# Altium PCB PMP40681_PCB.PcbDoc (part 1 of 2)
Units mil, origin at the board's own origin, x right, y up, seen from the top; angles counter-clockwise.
Board outline 1574.8 x 1574.8 mil, 4 copper layers (Top Layer, Signal Layer 1, Signal Layer 2, Bottom Layer), stack 67.2 mil thick; 42 components, 23 nets, 157 pads, 377 vias.
Unrouted connection lines stored in the file: 17.
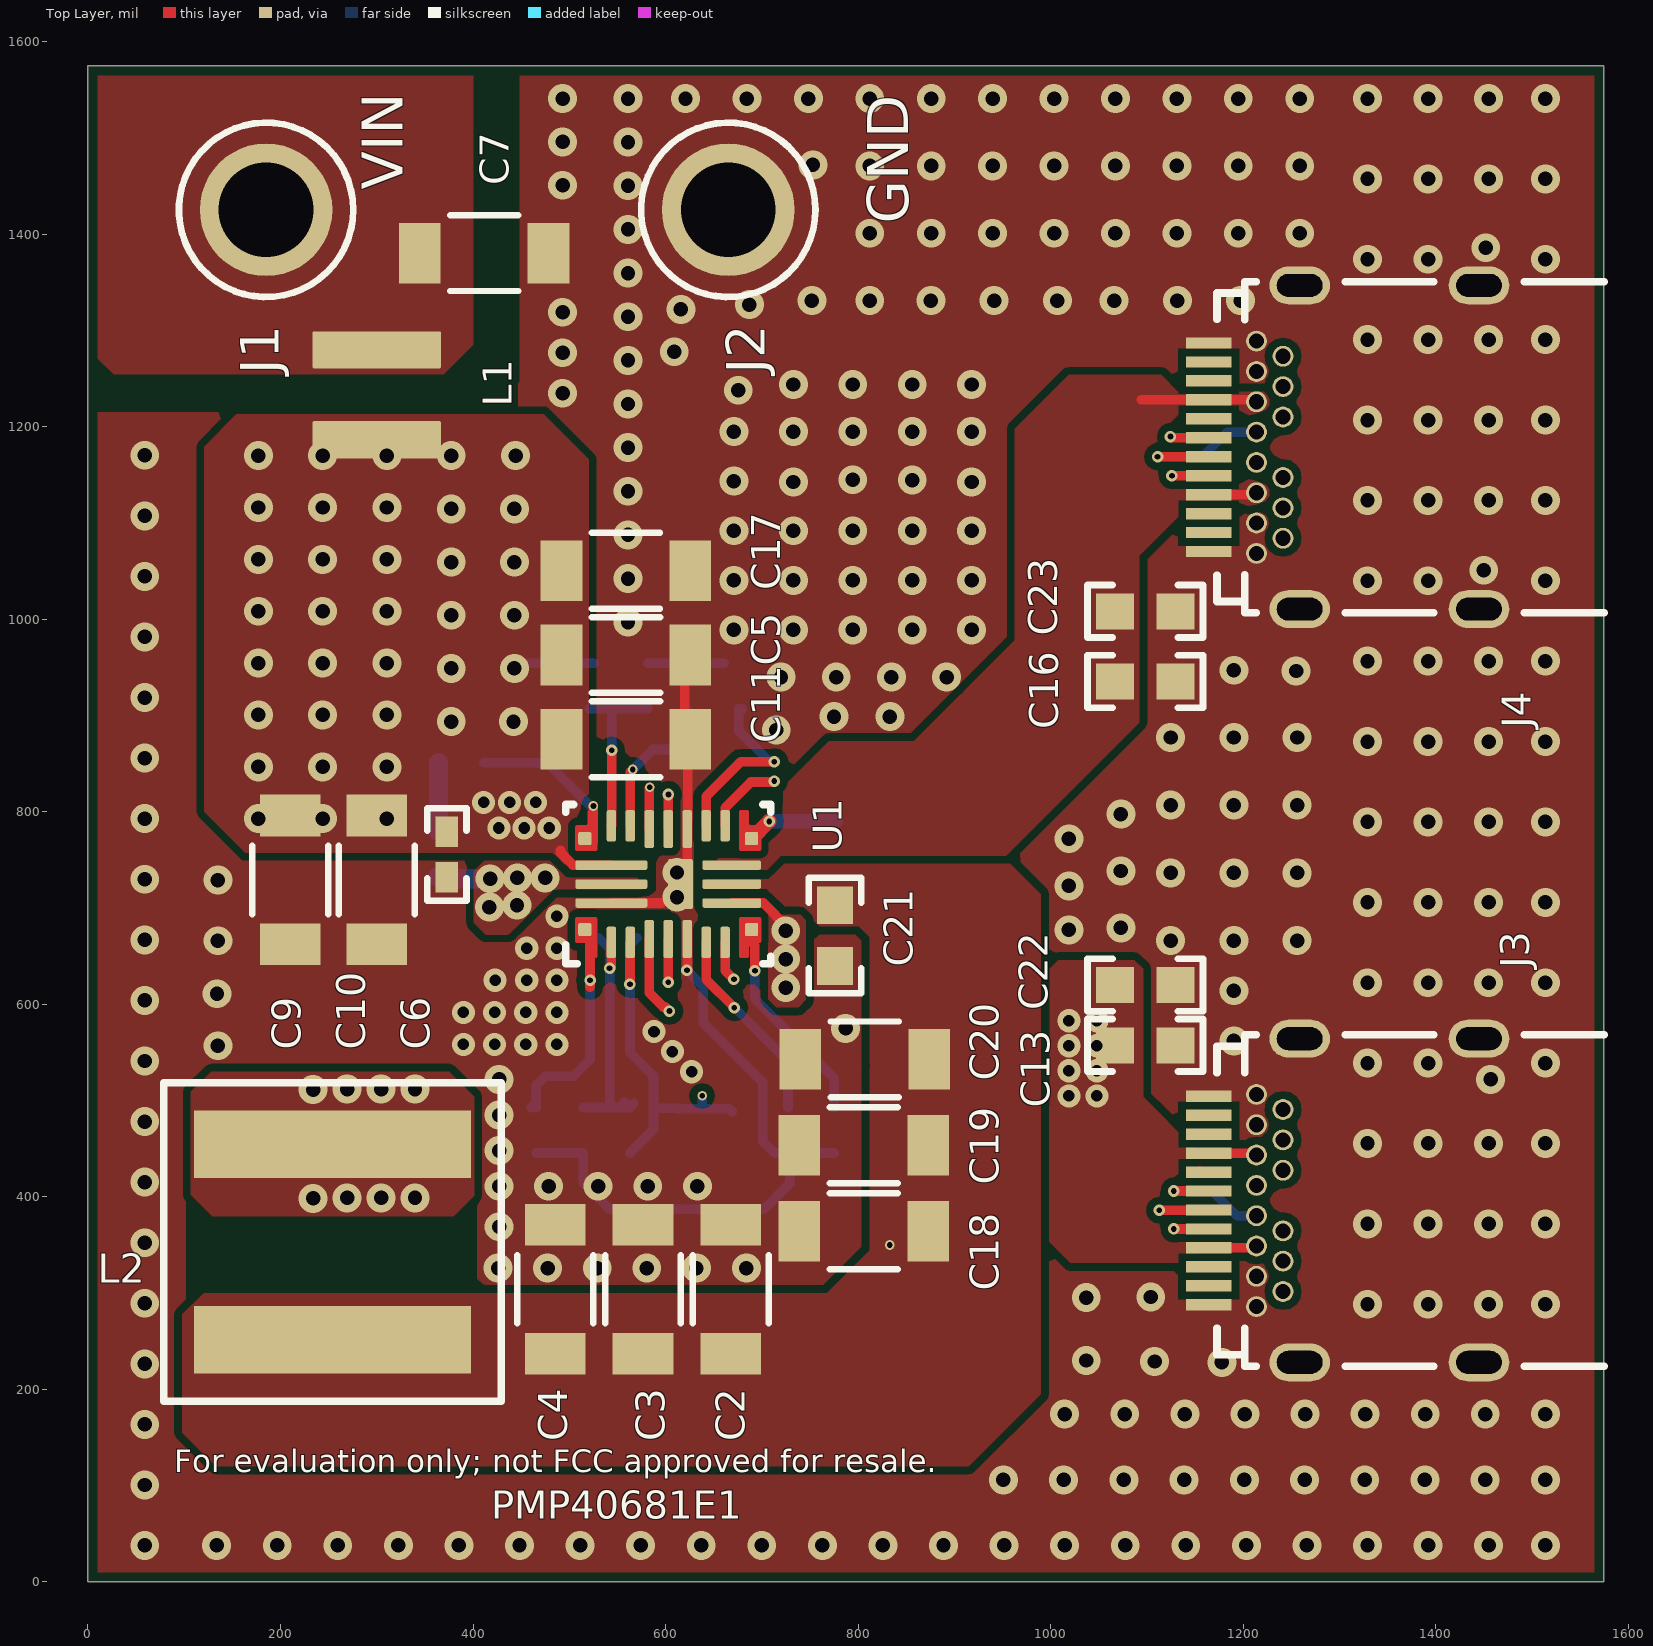
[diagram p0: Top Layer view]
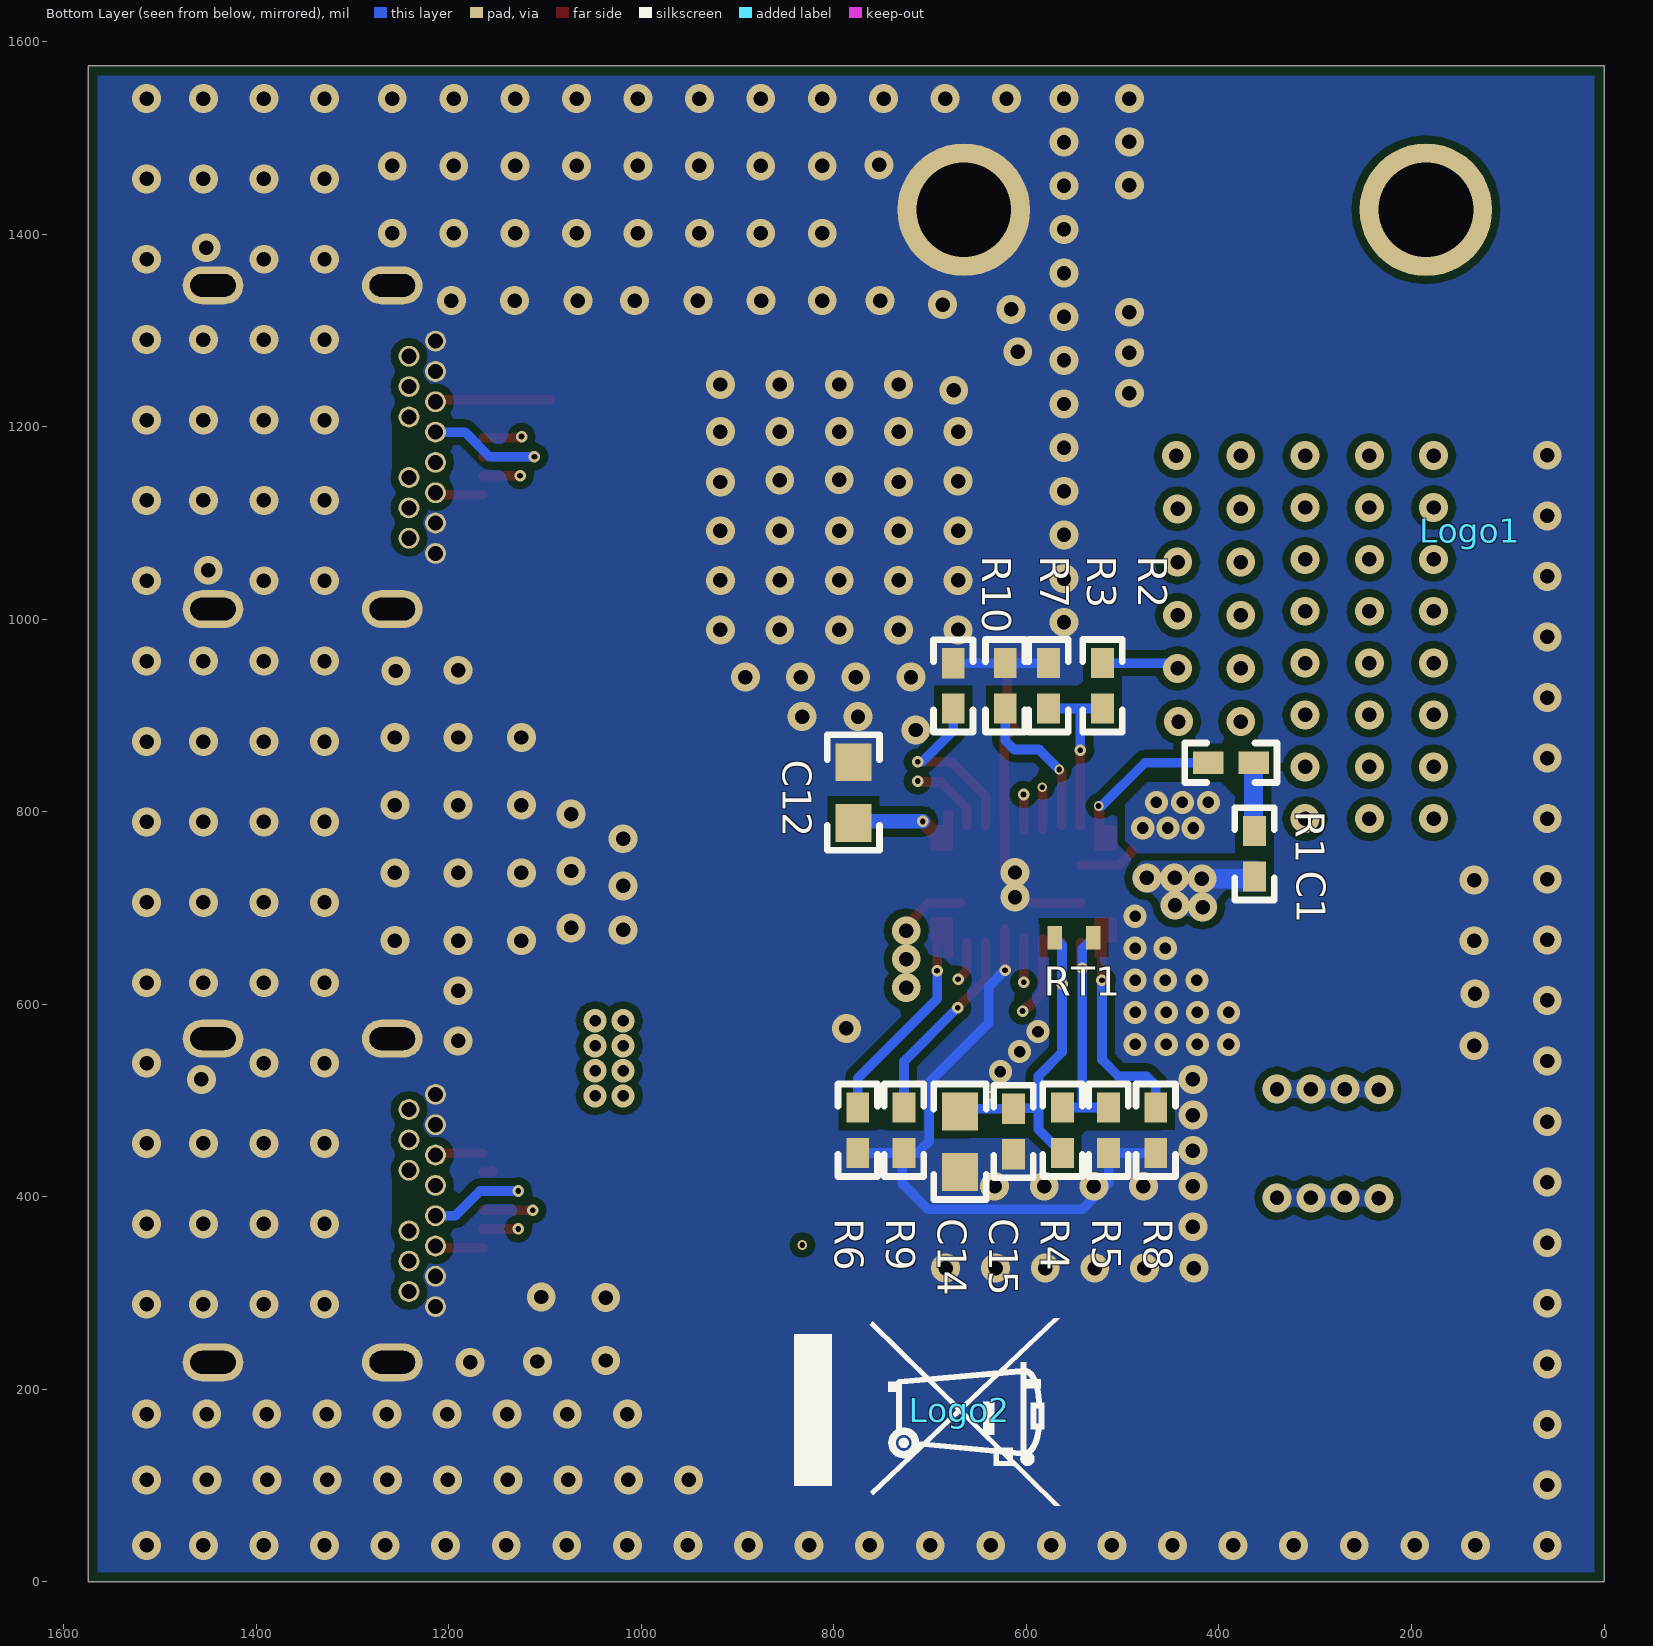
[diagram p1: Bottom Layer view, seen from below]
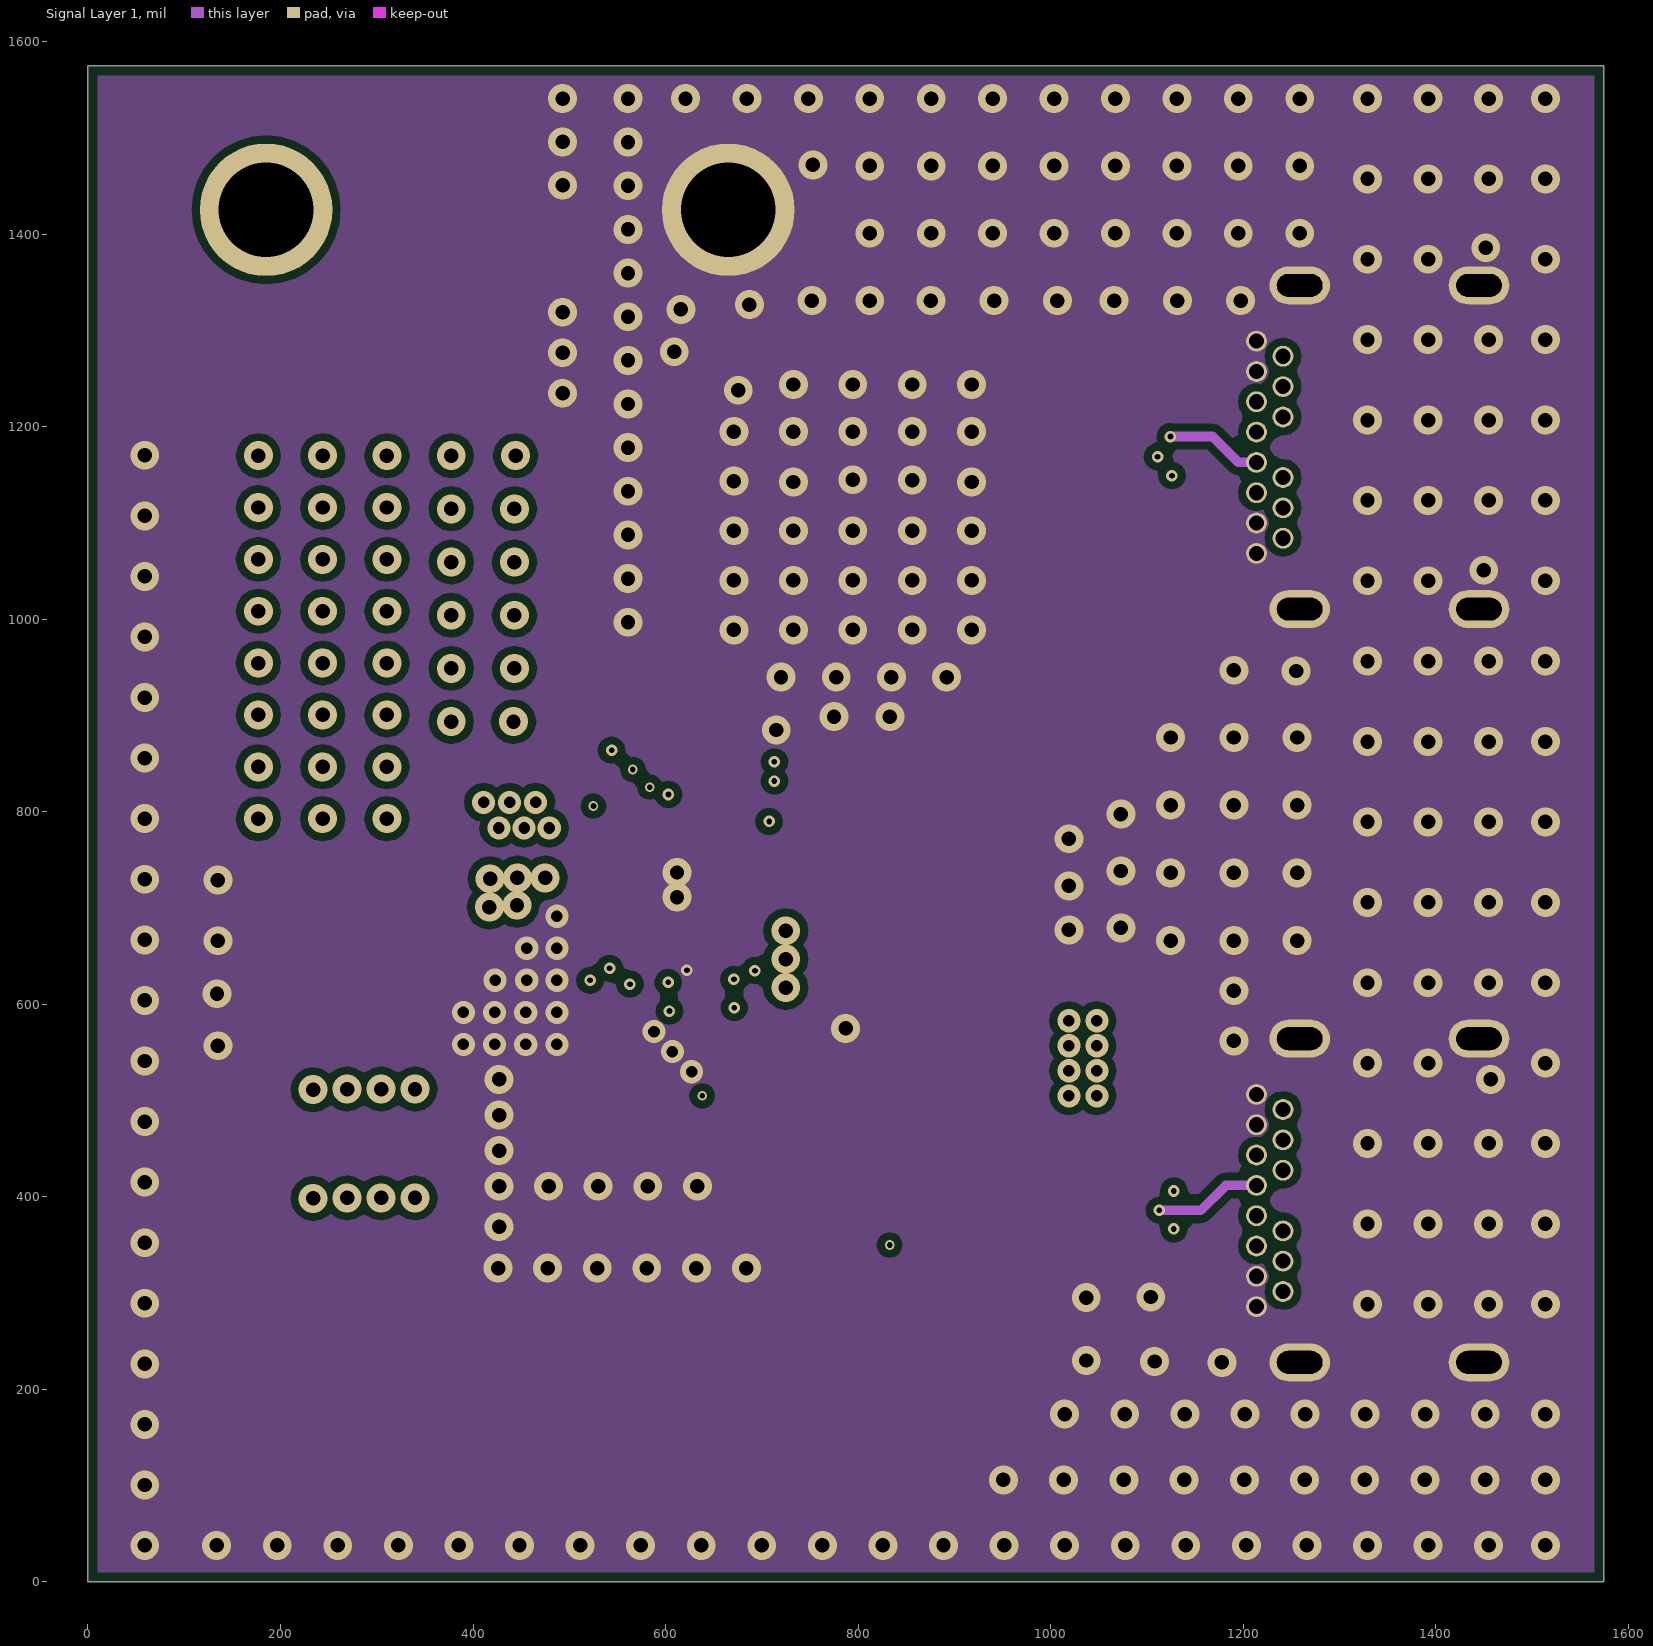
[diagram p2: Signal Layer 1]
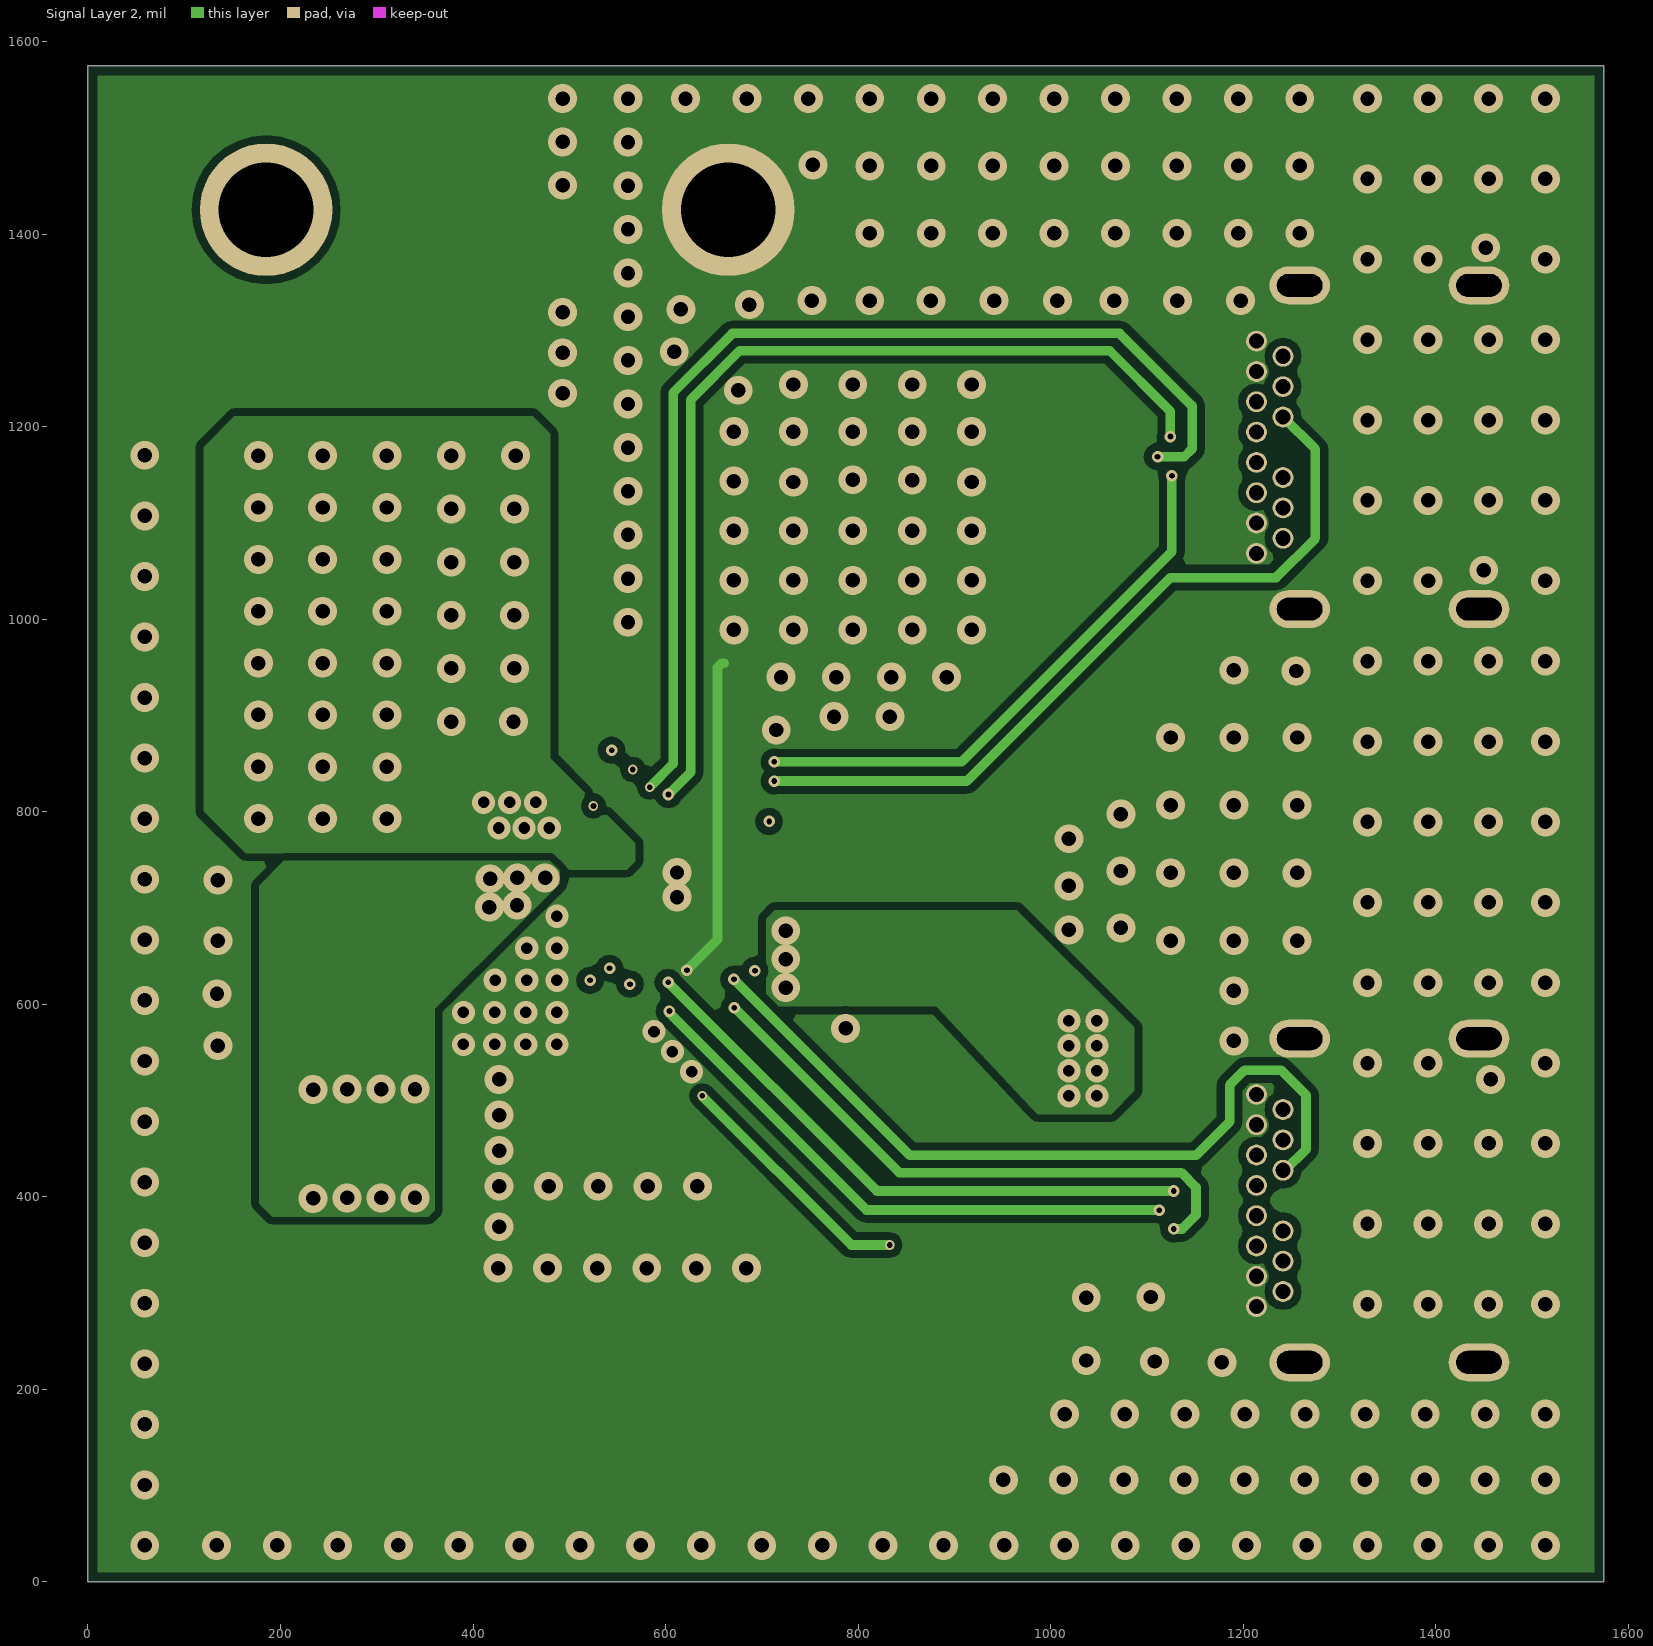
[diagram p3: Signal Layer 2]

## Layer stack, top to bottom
Top Solder: solder mask 0.4, Solder Resist, Dk 3.5
Top Layer: signal copper 2.8
Dielectric 1: prepreg 8, FR-4, Dk 4.2
Signal Layer 1: signal copper 2.8
Dielectric 2: core 40, FR-4, Dk 4.2
Signal Layer 2: signal copper 2.8
Dielectric 3: prepreg 8, FR-4, Dk 4.2
Bottom Layer: signal copper 2.8
Bottom Solder: solder mask 0.4, Solder Resist, Dk 3.5

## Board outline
0,0 0,1574.8 1574.8,1574.8 1574.8,0

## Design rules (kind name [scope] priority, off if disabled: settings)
AcuteAngle [All] p1: minimum=4.50000000000000E+0001 checktracksonly=FALSE
AssemblyTestPointUsage [All] p1: valid=2
BoardOutlineClearance BoardOutlineClearance_MountingHoles [OnCopper and InComponentClass('Mounting Holes')] p1: gap=25 ignorepadtopadclearanceinfootprint=FALSE
BoardOutlineClearance BoardOutlineClearance_Poly [OnCopper and IsPoly] p2: gap=10 ignorepadtopadclearanceinfootprint=FALSE
BoardOutlineClearance [OnCopper and Not InComponentClass('Logo') and not InComponentClass('FiducialMark') and not InRegion(1000,500,4000,800) and not InPoly] p3: gap=24 ignorepadtopadclearanceinfootprint=FALSE
Clearance Clearance_1 [All] p1: gap=8 ignorepadtopadclearanceinfootprint=FALSE
Clearance Clearance_Keepouts [((IsTrack Or IsArc) And Not InPoly) And IsFree and IsKeepOut vs ((IsTrack Or IsArc) And Not InPoly) And IsFree and IsKeepOut] p2: gap=0 ignorepadtopadclearanceinfootprint=FALSE
Clearance Clearance_Poly [InPolygon] p3: gap=10 ignorepadtopadclearanceinfootprint=TRUE
Clearance Clearance_FiducialMark [IsKeepOut and InComponentClass('FiducialMark') vs IsPad and InComponentClass('FiducialMark')] p4: gap=0 ignorepadtopadclearanceinfootprint=FALSE
Clearance [All] p5: gap=6 ignorepadtopadclearanceinfootprint=TRUE
ComponentClearance ComponentClearance_MountingHoles_FiducialMarks [InComponentClass('Mounting Holes') vs InComponentClass('FiducialMark')] p1: gap=50 collisioncheckmode=3 verticalgap=10 showdistances=FALSE
ComponentClearance ComponentClearance_Shunt [InComponentClass('Header') vs InComponentClass('Shunt')] p2: gap=0 collisioncheckmode=3 verticalgap=0 showdistances=FALSE
ComponentClearance ComponentClearance_Logo [InComponentClass('Logo')] p3: gap=50 collisioncheckmode=3 verticalgap=10 showdistances=FALSE
ComponentClearance ComponentClearance_ScrewToNut [(HasFootprint('NY PMS 440 0025 PH')) vs (HasFootprint('Keystone_1902C'))] p4: gap=5 collisioncheckmode=3 verticalgap=10 showdistances=FALSE
ComponentClearance ComponentClearance_MountingHoles [InComponentClass('Mounting Holes')] p5: gap=250 collisioncheckmode=3 verticalgap=100000 showdistances=FALSE
ComponentClearance ComponentClearance_SmallPassives [HasFootprint('0201*') or HasFootprint('0402*') or HasFootprint('0508') or HasFootprint('0603*') or HasFootprint('0612') or HasFootprint('0805*') or HasFootprint('0815*') or HasFootprint('0830*') or HasFootprint('1206*') or HasFootprint('1210*') or HasFootprint('1808*') or HasFootprint('1812*') or HasFootprint('1825*') or HasFootprint('2010*') or HasFootprint('2220*') or HasFootprint('2225*') or HasFootprint('2512*') or HasFootprint('2728*') or HasFootprint('3518*') vs HasFootprint('0201*') or HasFootprint('0402*') or HasFootprint('0508') or HasFootprint('0603*') or HasFootprint('0612') or HasFootprint('0805*') or HasFootprint('0815*') or HasFootprint('0830*') or HasFootprint('1206*') or HasFootprint('1210*') or HasFootprint('1808*') or HasFootprint('1812*') or HasFootprint('1825*') or HasFootprint('2010*') or HasFootprint('2220*') or HasFootprint('2225*') or HasFootprint('2512*') or HasFootprint('2728*') or HasFootprint('3518*')] p6: gap=10 collisioncheckmode=3 verticalgap=10 showdistances=FALSE
ComponentClearance ComponentClearance_THtoSMT [IsThruComponent vs IsSMTComponent] p7: gap=40 collisioncheckmode=3 verticalgap=30 showdistances=FALSE
ComponentClearance ComponentClearance_THtoTH [IsThruComponent vs IsThruComponent] p8: gap=30 collisioncheckmode=3 verticalgap=30 showdistances=FALSE
ComponentClearance [All] p9: gap=30 collisioncheckmode=3 verticalgap=10 showdistances=FALSE
DiffPairsRouting [All] p1: maxlimit=100 minlimit=8 mostfreqgap=10 toplayer_minwidth=10 toplayer_maxwidth=15 toplayer_prefwidth=10 midlayer1_minwidth=10 midlayer1_maxwidth=15 midlayer1_prefwidth=10 midlayer2_minwidth=10 midlayer2_maxwidth=15 midlayer2_prefwidth=10 bottomlayer_minwidth=10 bottomlayer_maxwidth=15 bottomlayer_prefwidth=10 maxuncoupledlength=1000
FabricationTestPointUsage TestPointUsage [All] p1: valid=2 allowmultiple=FALSE
FabricationTestpoint Testpoint [All] p1: side=3 testpointundercomponent=TRUE minsize=40 maxsize=100 preferedsize=60 minholesize=0 maxholesize=40 preferedholesize=32 testpointgrid=1 allowsidetop=TRUE allowsidebottom=TRUE usegrid=TRUE gridtolerance=0.01
FanoutControl Fanout_LCC [IsLCC] p1: bgadir=Out bgaviamode=Centered fanoutstyle=Auto fanoutdirection=Alternating viagrid=1 // Fanout_LCC (Default Rule)
FanoutControl Fanout_BGA [IsBGA] p2: bgadir=Out bgaviamode=Centered fanoutstyle=Auto fanoutdirection=Alternating viagrid=1 // Fanout_BGA (Default Rule)
FanoutControl Fanout_Default [All] p4: bgadir=Out bgaviamode=Centered fanoutstyle=Auto fanoutdirection=Alternating viagrid=1 // Fanout_Default (Default Rule)
FanoutControl Fanout_Small [(CompPinCount < 5)] p5: bgadir=Out bgaviamode=Centered fanoutstyle=Auto fanoutdirection=OutThenIn viagrid=1 // Fanout_Small (Default Rule)
HoleSize [All] p1: absolutevalues=TRUE maxlimit=251 minlimit=7.87 maxpercent=80.000 minpercent=20.000
HoleToHoleClearance [All] p1: gap=8 allowstackedmicrovias=TRUE
MinimumAnnularRing MinimumAnnularRing_ThermalPadVias [IsVia and InAnyComponent] p1: minimumring=3
MinimumAnnularRing [All] p2: minimumring=4
MinimumSolderMaskSliver MinimumSolderMaskSliver_Logo [InComponentClass('Logo') vs InComponentClass('Logo')] p1: minsoldermaskwidth=0.4
MinimumSolderMaskSliver [All] p2: minsoldermaskwidth=3.94
PlaneClearance [All] p1: clearance=15
PlaneConnect [All] p1: planeconnectstyle=Relief reliefexpansion=10 reliefentries=4 reliefconductorwidth=10 reliefairgap=10
PolygonConnect [All] p1: connectstyle=Direct reliefconductorwidth=10 reliefentries=4 polygonreliefangle="90 Angle" airgapwidth=10
RoutingVias ThermalPadVias [IsVia and InAnyComponent] p1: holewidth=7.87 width=19.68 viastyle="Through Hole" minholewidth=7.87 minwidth=19.68 maxholewidth=12.99 maxwidth=23.62
RoutingVias [All] p2: holewidth=16 width=30 viastyle="Through Hole" minholewidth=6 minwidth=10 maxholewidth=20 maxwidth=30
SilkToBoardRegionClearance [Not ((IsComment or IsDesignator) And (Hide <> 'False')) and not InRegion(1000,500,4000,800)] p1:
SilkToSilkClearance SilkToSilkClearance_Pb-FreeLogo [(HasFootprint('Pb-Free_Overlay_Medium') OR HasFootprint('Pb-Free_Overlay_Small')) vs (HasFootprint('Pb-Free_Overlay_Medium') OR HasFootprint('Pb-Free_Overlay_Small'))] p1: silktosilkclearance=0
SilkToSilkClearance [All] p2: silktosilkclearance=3.94
SilkToSolderMaskClearance SilkToComponentPadClearance [(IsPad or IsFill or IsRegion) and InAnycomponent] p1: minsilkscreentomaskgap=5 clearancetoexposedcopper=TRUE
SilkToSolderMaskClearance "Silk to Solder Mask Opening" [All] p2: minsilkscreentomaskgap=3.94 clearancetoexposedcopper=FALSE
SolderMaskExpansion [All] p1: expansion=1.97
UnRoutedNet [All] p1: checkbadconnections=TRUE
Width [All] p1: maxlimit=100 minlimit=6 preferedwidth=10 checkconnectedcopper=TRUE
12 further rules are at their usual default settings.

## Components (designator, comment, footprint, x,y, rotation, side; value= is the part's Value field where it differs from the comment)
C1 "GCM155R71H104KE02D" 0402 363,756.38 r90 bottom value=0.1uF
C2 "GCM31CR71A226KE02" 1206_180 667.79,304.1 r90 top value=22uF
C3 "GCM31CR71A226KE02" 1206_180 485.46,304.1 r90 top value=22uF
C4 "GCM31CR71A226KE02" 1206_180 576.62,304.1 r90 top value=22uF
C5 "CGA5L1X7R1H106K160AC" 1206_190 558.85,962.98 r0 top value=10uF
C6 "GCM155R71H104KE02D" 0402 372.81,755.62 r270 top value=0.1uF
C7 "CGA5L1X7R1H106K160AC" 1206_190 411.56,1380.4 r0 top value=10uF
C9 "CGA5L1X7R1H106K160AC" 1206_190 210,729.25 r270 top value=10uF
C10 "CGA5L1X7R1H106K160AC" 1206_190 300,729.25 r270 top value=10uF
C11 "CGA5L1X7R1H106K160AC" 1206_190 558.85,875.48 r0 top value=10uF
C12 "GRM188R71A225KE15J" 0603 779.77,820 r90 bottom value=2.2uF
C13 "GCM188R71C105KA64D" 0603 1098.38,557.45 r0 top value=1uF
C14 "GRM188R71A225KE15J" 0603 669.11,457.26 r270 bottom value=2.2uF
C15 "GCM155R71C104JA55D" 0402 613.41,468 r270 bottom value=0.1uF
C16 "GCM188R71C105KA64D" 0603 1098.38,935.37 r0 top value=1uF
C17 "CGA5L1X7R1H106K160AC" 1206_190 558.77,1050.48 r0 top value=10uF
C18 "GCM31CR71A226KE02" 1206_180 805.85,364.25 r180 top value=22uF
C19 "GCM31CR71A226KE02" 1206_180 805.85,453.55 r180 top value=22uF
C20 "GCM31CR71A226KE02" 1206_180 807,542.85 r180 top value=22uF
C21 "C0603C104K5RACAUTO" 0603 776,671.5 r270 top value=0.1uF
C22 "GCM188R71C104KA37J" 0603 1098.38,620 r0 top value=0.1uF
C23 "GCM188R71C104KA37J" 0603 1098.38,1008.37 r0 top value=0.1uF
J1 "1502-2" Keystone1502-2 185,1425.4 r0 top
J2 "1502-2" Keystone1502-2 665.11,1425.4 r0 top
J3 "632723300011" Wurth_632_723_300_011 1580.79,396.22 r90 top
J4 "632723300011" Wurth_632_723_300_011 1580.79,1178.74 r90 top
L1 "XAL4020-102MEB" XAL4020 300,1233.23 r270 top value=1uH
L2 "XAL8080-102MEB" XAL8080 254,353 r270 top value=1uH
Logo1 "FCC disclaimer" FCC_disclaimer 139,1092.13 r270 bottom
Logo2 "WEEE logo" WEEE_Minimum 669.11,178.49 r270 bottom
R1 "CRCW04020000Z0ED" 0402 387.62,851 r180 bottom value=0
R2 "CRCW040220K0JNED" 0402 521,931 r90 bottom value=20k
R3 "CRCW04025K10JNED" 0402 577,931 r270 bottom value=5.1k
R4 "CRCW040239K2FKED" 0402 562.64,469.24 r270 bottom value=39.2k
R5 "CRCW040218K7FKED" 0402 514.64,469.24 r90 bottom value=18.7k
R6 "CRCW04020000Z0ED" 0402 775.2,469.24 r270 bottom value=0
R7 "CRCW04028K87FKED" 0402 622,931 r270 bottom value=8.87k
R8 "CRCW04020000Z0ED" 0402 465.64,469.24 r270 bottom value=0
R9 "CRCW04025K10JNED" 0402 727.15,469.24 r90 bottom value=5.1k
R10 "CRCW04025K10JNED" 0402 676,930.88 r270 bottom value=5.1k
RT1 "NCP15WM474J03RC" 0402S 550.56,669.24 r0 bottom value=470k
U1 "TPS25850QRPQRQ1" RPQ0025A 602.76,724.95 r90 top

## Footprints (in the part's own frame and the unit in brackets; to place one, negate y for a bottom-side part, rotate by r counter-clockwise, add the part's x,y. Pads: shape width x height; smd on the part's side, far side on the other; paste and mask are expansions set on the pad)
0402 [mm] "0402 from SM-752 data"
  rect 0.8x0.6 smd: 1(-0.6,0) 2(0.6,0)
  silkscreen extent -1.22,-0.52 1.22,0.52, body extent -0.55,-0.3 0.55,0.3, height 0.6
0402S [mil] "Based on C0402S footprint from PADS legacy"
  rect 15x24 smd: 1(-20,0) 2(20,0)
  body extent -22,-12 22,12, height 24
0603 [mm] "0603 from SM-752 data"
  rect 1x0.95 smd: 1(-0.8,0) 2(0.8,0)
  silkscreen extent -1.52,-0.69 1.52,0.69, body extent -0.87,-0.47 0.87,0.47, height 1
1206_180 [mm] "1206_180"
  rect 1.1x1.6 smd: 1(-1.7,0) 2(1.7,0)
  silkscreen extent -0.9,-1 0.9,1, body extent -1.75,-0.95 1.75,0.95, height 1.8
1206_190 [mm] "1206_190"
  rect 1.1x1.6 smd: 1(-1.7,0) 2(1.7,0)
  silkscreen extent -0.9,-1 0.9,1, body extent -1.75,-0.95 1.75,0.95, height 1.9
FCC_disclaimer [mil]
Keystone1502-2 [mm] "Double Turret"
  round 3.5 hole 2.5: 1(0,0)
  silkscreen extent -2.3,-2.3 2.3,2.3, body extent -1.6,-1.6 1.59,1.6, height 5.62
RPQ0025A [mm] "VQFN-25"
  rrect29% 0.35x0.35 smd: 1(-1.2,2.2) 9(-1.2,-2.2) 13(1.2,-2.2) 21(1.2,2.2)
  rrect40% 0.825x0.25 smd: 2(-1.538,1.5) 3(-1.538,1) 7(-1.538,-1) 8(-1.538,-1.5) 14(1.538,-1.5) 15(1.538,-1) 19(1.538,1) 20(1.538,1.5)
  rrect40% 1x0.25 smd: 4(-1.45,0.5) 5(-1.45,0) 6(-1.45,-0.5) 16(1.45,-0.5) 17(1.45,0) 18(1.45,0.5)
  rrect40% 0.25x1.55 smd paste-1.55: 10(-0.5,-1.675) 11(0,-1.675) 12(0.5,-1.675)
  rrect40% 0.25x1.9 smd paste-1.55: 22(0.5,1.5) 23(0,1.5) 24(-0.5,1.5)
  rrect15% 1.325x0.65 smd paste-1.325: 25(0,-0.325)
  Top Layer region: -1.95,1.925 -1.95,2.075 -1.946,2.094 -1.935,2.11 -1.919,2.121 -1.9,2.125 -1.9,2.125 -1.6,2.125 -1.581,2.129 -1.565,2.14 -1.554,2.156 -1.55,2.175 -1.55,2.175 -1.55,2.4 -1.546,2.419 -1.535,2.435 -1.519,2.446 -1.5,2.45 -1.5,2.45 -0.925,2.45 -0.906,2.446 -0.89,2.435 -0.879,2.419 -0.875,2.4 -0.875,2.4 -0.875,1.925 -0.879,1.906 -0.89,1.89 -0.906,1.879 -0.925,1.875 -0.925,1.875 -1.9,1.875 -1.919,1.879 -1.935,1.89 -1.946,1.906 -1.95,1.925
  Top Layer region: -1.95,-1.925 -1.95,-2.075 -1.946,-2.094 -1.935,-2.11 -1.919,-2.121 -1.9,-2.125 -1.9,-2.125 -1.6,-2.125 -1.581,-2.129 -1.565,-2.14 -1.554,-2.156 -1.55,-2.175 -1.55,-2.175 -1.55,-2.4 -1.546,-2.419 -1.535,-2.435 -1.519,-2.446 -1.5,-2.45 -1.5,-2.45 -0.925,-2.45 -0.906,-2.446 -0.89,-2.435 -0.879,-2.419 -0.875,-2.4 -0.875,-2.4 -0.875,-1.925 -0.879,-1.906 -0.89,-1.89 -0.906,-1.879 -0.925,-1.875 -0.925,-1.875 -1.9,-1.875 -1.919,-1.879 -1.935,-1.89 -1.946,-1.906 -1.95,-1.925
  Top Layer region: 1.95,-1.925 1.95,-2.075 1.946,-2.094 1.935,-2.11 1.919,-2.121 1.9,-2.125 1.9,-2.125 1.6,-2.125 1.575,-2.132 1.557,-2.15 1.55,-2.175 1.55,-2.175 1.55,-2.4 1.546,-2.419 1.535,-2.435 1.519,-2.446 1.5,-2.45 1.5,-2.45 0.925,-2.45 0.906,-2.446 0.89,-2.435 0.879,-2.419 0.875,-2.4 0.875,-2.4 0.875,-1.925 0.882,-1.9 0.9,-1.882 0.925,-1.875 0.925,-1.875 1.9,-1.875 1.919,-1.879 1.935,-1.89 1.946,-1.906 1.95,-1.925
  Top Layer region: 1.95,1.925 1.95,2.075 1.946,2.094 1.935,2.11 1.919,2.121 1.9,2.125 1.9,2.125 1.6,2.125 1.575,2.132 1.557,2.15 1.55,2.175 1.55,2.175 1.55,2.4 1.546,2.419 1.535,2.435 1.519,2.446 1.5,2.45 1.5,2.45 0.925,2.45 0.906,2.446 0.89,2.435 0.879,2.419 0.875,2.4 0.875,2.4 0.875,1.925 0.882,1.9 0.9,1.882 0.925,1.875 0.925,1.875 1.9,1.875 1.919,1.879 1.935,1.89 1.946,1.906 1.95,1.925
  silkscreen extent -2.1,-2.7 2.1,2.7, body extent -1.75,-2.25 1.75,2.25, height 1
WEEE_Minimum [mil] "WEEElie bin"
  silkscreen extent -95,-172 99,104
Wurth_632_723_300_011 [mm] "Connector, Receptacle, USB Type C, R/A"
  rect 0.3x1.2 smd: A1(-2.75,10.58) A2(-2.25,10.58) A3(-1.75,10.58) A4(-1.25,10.58) A5(-0.75,10.58) A6(-0.25,10.58) A7(0.25,10.58) A8(0.75,10.58) A9(1.25,10.58) A10(1.75,10.58) A11(2.25,10.58) A12(2.75,10.58)
  round 0.55 hole 0.4: B1(2.8,9.32) B2(2.4,8.62) B3(1.6,8.62) B4(1.2,9.32) B5(0.8,8.62) B6(0.4,9.32) B7(-0.4,9.32) B8(-0.8,8.62) B9(-1.2,9.32) B10(-1.6,8.62) B11(-2.4,8.62) B12(-2.8,9.32) M1(2,9.32) M2(-2,9.32)
  rrect100% 1x1.6 hole 0.6 slot 1.2 at 90 deg: S1(-4.27,8.18) S2(-4.27,3.45) S3(4.27,3.45) S4(4.27,8.18)
  silkscreen extent -4.37,0.15 4.37,10.36, body extent -4.37,-0.96 4.37,10.83, height 3.07
XAL4020 [mm] "Coilcraft XAL4020 01/14/18"
  rrect10% 0.98x3.4 smd: 1(-1.185,0) 2(1.185,0)
  body extent -2.15,-2.15 2.15,2.15, height 2.11
XAL8080 [mm] "Coilcraft"
  rect 1.78x7.31 smd: 1(-2.58,0) 2(2.58,0)
  silkscreen extent -4.2,-4.45 4.2,4.45, body extent -4.15,-4.4 4.15,4.4, height 8

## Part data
C1: library part CMP-0006356-1, "CAP, CERM, 0.1 uF, 50 V, +/- 10%, X7R, AEC-Q200 Grade 1, 0402", Cap_Case=0402, Manufacturer=MuRata, Supplier Part Number 1=490-10672-1-ND, TempCo=X7R, Tolerance_%=10%, Value1=Unknown, Value2=50V, ValueDisplayed=0.1uF
C2 C3 C4 C18 C19 C20: library part CMP-0008811-1, "CAP, CERM, 22 uF, 10 V, +/- 10%, X7R, AEC-Q200 Grade 1, 1206", Cap_Case=1206, Manufacturer=MuRata, TempCo=X7R, Tolerance_%=10%, Value1=Unknown, Value2=10V, ValueDisplayed=22uF
C5 C7 C9 C10 C11 C17: library part CMP-0085950-1, "CAP, CERM, 10 µF, 50 V,+/- 10%, X7R, AEC-Q200 Grade 1, 1206", Cap_Case=1206, Manufacturer=TDK, TempCo=X7R, Tolerance_%=10%, Value2=50V, ValueDisplayed=10µF
C6: library part CMP-0006356-2, "CAP, CERM, 0.1 uF, 50 V, +/- 10%, X7R, AEC-Q200 Grade 1, 0402", Cap_Case=0402, Manufacturer=MuRata, Supplier Part Number 1=490-10672-1-ND, TempCo=X7R, Tolerance_%=10%, Value1=Unknown, Value2=50V, ValueDisplayed=0.1uF
C12 C14: library part CMP-0084284-1, "CAP, CERM, 2.2 µF, 10 V,+/- 10%, X7R, AEC-Q200 Grade 1, 0603", Cap_Case=0603, Manufacturer=MuRata, TempCo=X7R, Tolerance_%=10%, Value2=10V, ValueDisplayed=2.2µF
C13 C16: library part CMP-0007136-3, "CAP, CERM, 1 uF, 16 V, +/- 10%, X7R, AEC-Q200 Grade 1, 0603", Cap_Case=0603, Manufacturer=MuRata, Supplier Part Number 1=490-5241-6-ND, TempCo=X7R, Tolerance_%=10%, Value1=Unknown, Value2=16V, ValueDisplayed=1uF
C15: library part CMP-0080702-1, "CAP, CERM, 0.1 µF, 16 V,+/- 5%, X7R, AEC-Q200 Grade 1, 0402", Cap_Case=0402, Manufacturer=MuRata, Supplier Part Number 1=490-16433-1-ND, TempCo=X7R, Tolerance_%=5%, Value2=16V, ValueDisplayed=0.1µF
C21: library part CMP-0079602-1, "CAP, CERM, 0.1 µF, 50 V,+/- 10%, X7R, AEC-Q200 Grade 1, 0603", Cap_Case=0603, Manufacturer=Kemet, Supplier Part Number 1=399-6856-1-ND, TempCo=X7R, Tolerance_%=10%, Value2=50V, ValueDisplayed=0.1µF
C22 C23: library part CMP-0007135-3, "CAP, CERM, 0.1 uF, 16 V, +/- 10%, X7R, AEC-Q200 Grade 1, 0603", Cap_Case=0603, Manufacturer=MuRata, Supplier Part Number 1=490-8015-1-ND, TempCo=X7R, Tolerance_%=10%, Value1=Unknown, Value2=16V, ValueDisplayed=0.1uF
J1 J2: library part CMP-0055113-1, "Terminal, Turret, TH, Double", Manufacturer=Keystone, Supplier Part Number 1=36-1502-2-ND
J3 J4: library part CMP-0080891-1, "Connector, Receptacle, USB Type C, R/A", Color=Black, Current_A=3A, Manufacturer="Wurth Elektronik", Supplier Part Number 1=732-9618-1-ND, Voltage_V=5V
L1: library part CMP-0060983-2, "Inductor, Shielded, Composite, 1 µH, 8.75 A, 0.01 ohm, AEC-Q200 Grade 1, SMD", Manufacturer=Coilcraft, Value1="0.01 ohm", Value2=8.75A, ValueDisplayed=1uH
L2: library part CMP-0061059-1, "Inductor, Shielded, Composite, 1 uH, 31.38 A, 0.0021 ohm, SMD", Manufacturer=Coilcraft, Supplier Part Number 1=994-XAL8080-102MEB, Value1="0.0021 ohm", Value2=31.38A, ValueDisplayed=1uH
Logo1: library part CMP-0074847-1, "FCC_disclaimer"
Logo2: library part CMP-0074769-1
R1 R6 R8: library part CMP-0026822-3, "RES, 0, 5%, 0.063 W, AEC-Q200 Grade 0, 0402", Manufacturer=Vishay-Dale, Power_W=63mW, Supplier Part Number 1=541-0.0JCT-ND, TempCo="200 ppm/C", Tolerance_%=5%, Value2=0.063W, Value_Code=0000, ValueDisplayed=0
R2: library part CMP-0026875-3, "RES, 20 k, 5%, 0.063 W, AEC-Q200 Grade 0, 0402", Manufacturer=Vishay-Dale, Power_W=63mW, Supplier Part Number 1=541-20KJCT-ND, TempCo="200 ppm/C", Tolerance_%=5%, Value2=0.063W, Value_Code=20k0, ValueDisplayed=20k
R3 R9 R10: library part CMP-0026951-5, "RES, 5.1 k, 5%, 0.063 W, AEC-Q200 Grade 0, 0402", Manufacturer=Vishay-Dale, Power_W=63mW, Supplier Part Number 1=541-5.1KJCT-ND, TempCo="200 ppm/C", Tolerance_%=5%, Value2=0.063W, Value_Code=5k10, ValueDisplayed=5.1k
R4: library part CMP-0026327-2, "RES, 39.2 k, 1%, 0.063 W, AEC-Q200 Grade 0, 0402", Manufacturer=Vishay-Dale, Power_W=63mW, Supplier Part Number 1=541-39.2KLCT-ND, TempCo="100 ppm/C", Tolerance_%=1%, Value2=0.063W, Value_Code=39k2, ValueDisplayed=39.2k
R5: library part CMP-0026060-3, "RES, 18.7 k, 1%, 0.063 W, AEC-Q200 Grade 0, 0402", Manufacturer=Vishay-Dale, Power_W=63mW, Supplier Part Number 1=541-18.7KLCT-ND, TempCo="100 ppm/C", Tolerance_%=1%, Value2=0.063W, Value_Code=18k7, ValueDisplayed=18.7k
R7: library part CMP-0026592-2, "RES, 8.87 k, 1%, 0.063 W, AEC-Q200 Grade 0, 0402", Manufacturer=Vishay-Dale, Power_W=63mW, Supplier Part Number 1=541-8.87KLCT-ND, TempCo="100 ppm/C", Tolerance_%=1%, Value2=0.063W, Value_Code=8k87, ValueDisplayed=8.87k
RT1: library part CMP-0002542-1, "Thermistor NTC, 470k ohm, 5%, 0402", Manufacturer=MuRata, Power_W=100mW, Supplier Part Number 1=490-2407-1-ND, Tolerance_%=5%
U1: library part CMP-0860365-2, "Dual 3A USB Type-C Charging Ports Controller with Programmable Current Limit and Thermal Management, RPQ0025A (VQFN-25)", Alternate Manufacturer="Texas Instruments"

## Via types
v1: diameter 30, hole 15, Top Layer to Bottom Layer, 321 vias
v2: diameter 24, hole 12, Top Layer to Bottom Layer, 28 vias
v3: diameter 12, hole 6, Top Layer to Bottom Layer, tented both sides, 14 vias
v4: diameter 12, hole 6, Top Layer to Bottom Layer, tented bottom, 6 vias
v5: diameter 10, hole 6, Top Layer to Bottom Layer, tented both sides, 5 vias
v6: diameter 24, hole 12, Top Layer to Bottom Layer, tented both sides, 3 vias

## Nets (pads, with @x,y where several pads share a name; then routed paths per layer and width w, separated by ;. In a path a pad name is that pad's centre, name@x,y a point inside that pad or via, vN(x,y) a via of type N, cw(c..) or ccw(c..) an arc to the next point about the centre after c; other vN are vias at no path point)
BOOT: R1.1 U1.21 | length 169.9
  Top Layer w10: 524.85,768.55 525,768.69 v5(525,806)
  Bottom Layer w10: R1.1@411.24,851 477.03,851 522.03,806 v5(525,806)
EN: R2.1 R3.2 U1.20 | length 229.1
  Top Layer w10: U1.20@543.71,785.48 544,785.77 v3(544,864)
  Bottom Layer w10: R2.1@521,907.38 581.38,907.38 581.5,907.25 546,907.25 ; 535.96,907.25 546,907.25 ; v3(544,864) 544,904.67 543.71,904.96 546,907.25
INPUT: C7.1 J1.1 L1.1
NetC1_2: C1.2 R1.2 | length 71.4
  Bottom Layer w20: C1.2@363,780 364,781 R1.2@364,851
NetR6_1: R6.1 U1.9 | length 225.8
  Top Layer w10: U1.9@689.38,677.71 689.56,677.53 683,670.97 692.82,661.15 v3(692.82,635)
  Bottom Layer w10: v3(692.82,635) 692.82,605.74 775.2,523.37 R6.1@775.2,492.86
NetR7_2: R7.2 U1.19 | length 161.4
  Top Layer w10: U1.19@563.39,785.48 563.39,841.39 v5(566,844)
  Bottom Layer w10: v5(566,844) 586.75,864.75 612.75,864.75 622,874 R7.2@622,907.38
OUT: C12.1 U1.13 | length 94.9
  Top Layer w15: U1.13@689.38,772.19 707.18,790 v3(707.65,790)
  Bottom Layer w15: v3(707.65,790) C12.1@776.94,790
PA_BUS: C13.1 C22.1 J3.A4 J3.A9 J3.B4 J3.B9 U1.10 | length 173.6
  Top Layer w10: U1.10@668.71,705.27 701.69,705.27 725.85,681.1 v1@725.85,675.48 ; J3.A4@1164.25,347.01 1211.89,347.01 J3.B9@1213.86,348.98 ; J3.A9@1164.25,445.43 1211.89,445.43 J3.B4@1213.86,443.46
  other v1: 724.85,617.48 724.85,646.98 724.85,676.48
  other v2: 1019,505 1048,505 1019,531 1048,531 1019,557 1048,557 1019,583 1048,583
PA_CC1: J3.A5 R9.2 U1.7 | length 857.8
  Top Layer w10: U1.7@642.13,664.42 642.13,625.75 v3(671.38,596.5) ; v4(1127.96,366.69) J3.A5@1164.25,366.69
  Signal Layer 2 w10: v3(671.38,596.5) 842.77,425.11 1135.83,425.11 1151,409.94 1151,381.12 1136.58,366.69 v4(1127.96,366.69)
  Bottom Layer w10: v3(671.38,596.5) 727.15,540.73 R9.2@727.15,492.86
PA_CC2: J3.B5 U1.8 | length 871.1
  Top Layer w10: U1.8@661.82,664.42 661.82,635.18 v3(671,626)
  Signal Layer 2 w10: v3(671,626) 853.89,443.11 1151.11,443.11 1185.96,477.96 1185.96,516 1201.6,531.65 1239.36,531.65 1265.24,505.76 1265.24,449.34 1243.62,427.72 J3.B5@1241.42,427.72
PA_DM: J3.A7 J3.B7 U1.5 | length 789.8
  Top Layer w10: v3(602.76,622.87) U1.5@602.76,667.86 ; v4(1127.96,406.11) v4(1127.96,406.11) J3.A7@1164.25,406.06
  Signal Layer 2 w10: v3(602.76,622.87) 819.52,406.11 v4(1127.96,406.11)
  Bottom Layer w10: v4@1130.96,406.11 1167.7,406.11 1193.33,380.47 J3.B7@1213.86,380.47
PA_DP: J3.A6 J3.B6 U1.4 | length 843.5
  Top Layer w10: U1.4@583.08,667.86 583.08,611.92 597.77,597.23 599.77,597.23 v3(604,593) ; v4(1112.96,386.11) 1163.98,386.11 J3.A6@1164.25,386.38
  Signal Layer 1 w10: v4(1112.96,386.11) 1156.11,386.11 1181.97,411.97 J3.B6@1213.86,411.97
  Signal Layer 2 w10: v3(604,593) 604,591 808.62,386.38 1112.69,386.38 v4(1112.96,386.11)
PB_BUS: C16.1 C23.1 J4.A4 J4.A9 J4.B4 J4.B9 U1.12 | length 171
  Top Layer w10: 1094.06,1227.95 J4.A9@1164.25,1227.95 1211.89,1227.95 J4.B4@1213.86,1225.98 ; J4.A4@1164.25,1129.53 1211.89,1129.53 J4.B9@1213.86,1131.5
PB_CC1: J4.A5 R10.2 U1.15 | length 816.1
  Top Layer w10: U1.15@642.13,785.48 642.13,816.13 678,852 v3(713,852) ; v4(1125.96,1149.21) J4.A5@1164.25,1149.21
  Signal Layer 2 w10: v3(713,852) 907.65,852 1125.96,1070.31 v4(1125.96,1149.21)
  Bottom Layer w10: R10.2@676,907.25 R10.2@676,902.98 ; R10.2@679.85,907.25 679.85,906.83 R10.2@676,902.98 ; v3(713,852) 708.4,852 676,884.4 R10.2@676,902.98
PB_CC2: J4.B5 U1.14 | length 887.9
  Top Layer w10: U1.14@661.82,785.48 661.82,804.19 688.63,831 712,831 v3(713,832)
  Signal Layer 2 w10: v3(713,832) 912.91,832 913.01,831.9 1124.43,1043.32 1234.18,1043.32 1274.96,1084.1 1274.96,1176.69 J4.B5@1241.42,1210.24
PB_DM: J4.A7 J4.B7 U1.17 | length 1168.3
  Top Layer w10: U1.17@602.76,782.04 602.76,817.76 v3(603,818) ; v4(1124.46,1189.85) 1125.72,1188.58 J4.A7@1164.25,1188.58
  Signal Layer 1 w10: v4(1124.46,1189.85) 1168.3,1189.85 1195.16,1162.99 J4.B7@1213.86,1162.99
  Signal Layer 2 w10: v3(603,818) 626,841 626,1228.05 676.95,1279 1061.43,1279 1124.46,1215.97 v4(1124.46,1189.85)
PB_DP: J4.A6 J4.B6 U1.18 | length 1299.9
  Top Layer w10: U1.18@583.08,782.04 583.08,825.08 v5(583.63,825.63) ; v4@1116.1,1168.85 1116.15,1168.9 J4.A6@1164.25,1168.9
  Signal Layer 2 w10: v5(583.63,825.63) 608,850 608,1235.5 669.5,1297 1071.67,1297 1147,1221.67 1147,1177.04 1138.81,1168.85 v4(1111.1,1168.85)
  Bottom Layer w10: v4@1116.1,1168.85 1157.66,1168.85 1183.3,1194.49 J4.B6@1213.86,1194.49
